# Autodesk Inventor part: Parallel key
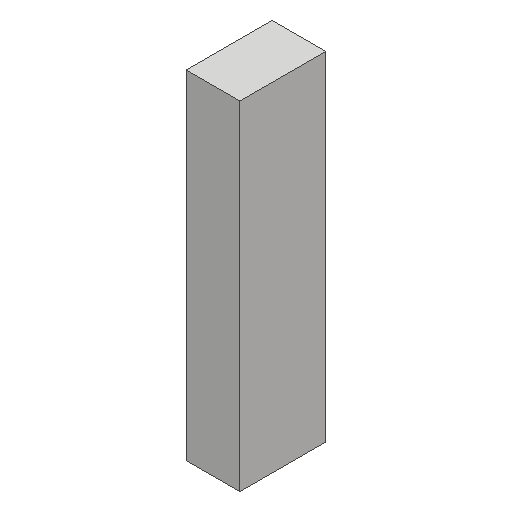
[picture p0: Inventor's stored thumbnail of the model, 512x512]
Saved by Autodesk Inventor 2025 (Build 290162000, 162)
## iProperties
Created: 2016-05
Part Number: Parallel key
Material: Generic
Document SubType Name: Modeling
Designer: CADCIM
Density: 1 g/cm^3
Appearance: Default
Author: CADCIM
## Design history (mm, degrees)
sketch "Sketch1"
  geometry: L1 (0, 0)-(16, 0); L2 (16, 0)-(16, -63); L3 (16, -63)-(0, -63); L4 (0, -63)-(0, 0)
  constraints: 8 end point, 2 parallel, 1 horizontal, 1 perpendicular
  dimensions: "d0" = 63 distance of L3.end L1.start; "d1" = 16 distance of L2.end L3.end
extrude "Extrusion1" new body sketch "Sketch1" distance "d2" = 10; taper "d3" = 0 deg
body "Solid1"
